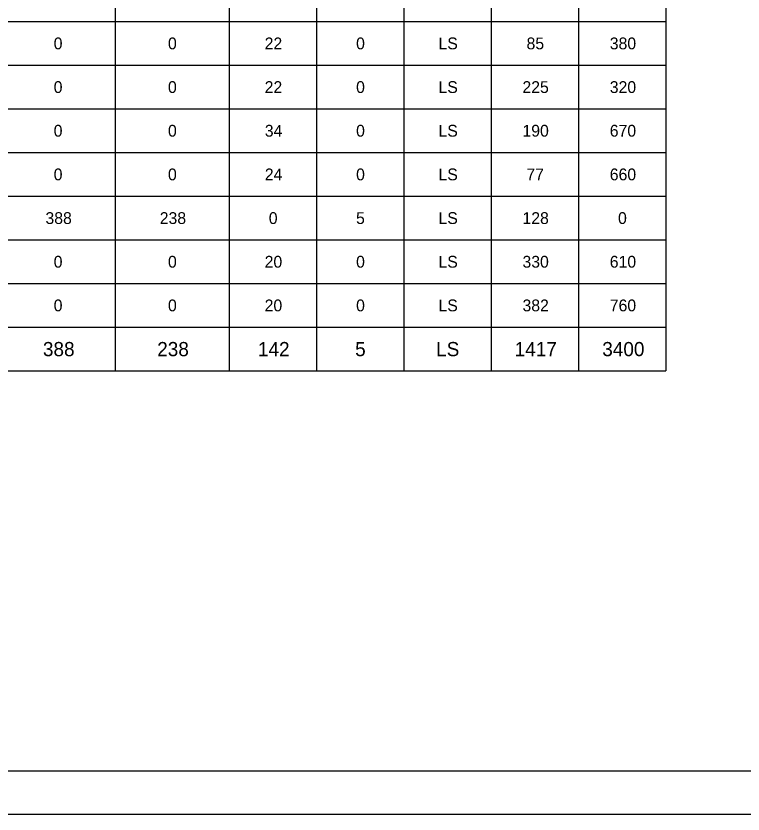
# Model space of a CAD drawing. Extents: x 0 to 34, y 0 to 22.
# Drawn here: x 17.01 to 25.51, y 0 to 9.32 of the extents above; entities that cross this region are included whole.
import ezdxf

# ---------------------------------------------------------------- set-up
doc = ezdxf.new("R2010")
doc.units = 0
for name, color, linetype in [('SH_Border', 7, 'Continuous'), ('SH_Cut_Line', 7, 'Continuous'), ('SH_Text', 7, 'Continuous')]:
    doc.layers.add(name, color=color, linetype=linetype)

msp = doc.modelspace()

# ---------------------------------------------------------------- linework, layer by layer
at = {"layer": 'SH_Border'}
msp.add_lwpolyline([(1.5, 21.5), (33.5, 21.5), (33.5, 0.5), (1.5, 0.5)], close=True, dxfattribs=at)
at = {"layer": 'SH_Cut_Line'}
msp.add_lwpolyline([(0, 0), (34, 0), (34, 22), (0, 22)], close=True, dxfattribs=at)
at = {"layer": 'SH_Text'}
for p, q in [((21.545, 21), (21.545, 5.175)), ((23.585, 21), (23.585, 5.175)), ((24.605, 21), (24.605, 5.175)), ((18.17, 20.745), (18.17, 5.175)), ((19.505, 20.745), (19.505, 5.175)), ((20.525, 20.745), (20.525, 5.175)), ((22.565, 20.745), (22.565, 5.175)), ((2, 9.255), (24.605, 9.255)), ((2, 8.745), (24.605, 8.745)), ((2, 8.235), (24.605, 8.235)), ((2, 7.725), (24.605, 7.725)), ((2, 7.215), (24.605, 7.215)), ((2, 6.705), (24.605, 6.705)), ((2, 6.195), (24.605, 6.195)), ((2, 5.685), (24.605, 5.685)), ((2, 5.175), (24.605, 5.175))]:
    msp.add_line(p, q, dxfattribs=at)

# ---------------------------------------------------------------- texts
for s, height, p in [('0', 0.138, (17.4535, 8.931)), ('0', 0.138, (18.7885, 8.931)), ('22', 0.138, (19.918, 8.931)), ('0', 0.138, (20.986, 8.931)), ('LS', 0.138, (21.9485, 8.931)), ('85', 0.138, (22.9771, 8.931)), ('380', 0.138, (23.9495, 8.931)), ('0', 0.138, (17.4535, 8.421)), ('0', 0.138, (18.7885, 8.421)), ('22', 0.138, (19.918, 8.421)), ('0', 0.138, (20.986, 8.421)), ('LS', 0.138, (21.9485, 8.421)), ('225', 0.138, (22.9289, 8.421)), ('320', 0.138, (23.9495, 8.421)), ('0', 0.138, (17.4535, 7.911)), ('0', 0.138, (18.7885, 7.911)), ('34', 0.138, (19.9196, 7.911)), ('0', 0.138, (20.986, 7.911)), ('LS', 0.138, (21.9485, 7.911)), ('190', 0.138, (22.9295, 7.911)), ('670', 0.138, (23.9495, 7.911)), ('0', 0.138, (17.4535, 7.401)), ('0', 0.138, (18.7885, 7.401)), ('24', 0.138, (19.9196, 7.401)), ('0', 0.138, (20.986, 7.401)), ('LS', 0.138, (21.9485, 7.401)), ('77', 0.138, (22.9751, 7.401)), ('660', 0.138, (23.9495, 7.401)), ('388', 0.138, (17.3571, 6.891)), ('238', 0.138, (18.6921, 6.891)), ('0', 0.138, (19.966, 6.891)), ('5', 0.138, (20.9853, 6.891)), ('LS', 0.138, (21.9485, 6.891)), ('128', 0.138, (22.9296, 6.891)), ('0', 0.138, (24.046, 6.891)), ('0', 0.138, (17.4535, 6.381)), ('0', 0.138, (18.7885, 6.381)), ('20', 0.138, (19.9177, 6.381)), ('0', 0.138, (20.986, 6.381)), ('LS', 0.138, (21.9485, 6.381)), ('330', 0.138, (22.9295, 6.381)), ('610', 0.138, (23.9495, 6.381)), ('0', 0.138, (17.4535, 5.871)), ('0', 0.138, (18.7885, 5.871)), ('20', 0.138, (19.9177, 5.871)), ('0', 0.138, (20.986, 5.871)), ('LS', 0.138, (21.9485, 5.871)), ('382', 0.138, (22.9298, 5.871)), ('760', 0.138, (23.9495, 5.871)), ('388', 0.1656, (17.3277, 5.3472)), ('238', 0.1656, (18.6627, 5.3472)), ('142', 0.1656, (19.8398, 5.3472)), ('5', 0.1656, (20.9749, 5.3472)), ('LS', 0.1656, (21.921, 5.3472)), ('1417', 0.1656, (22.8387, 5.3472)), ('3400', 0.1656, (23.8619, 5.3472))]:
    msp.add_text(s, height=height, dxfattribs=at).set_placement(p)

doc.saveas('drawing.dxf')
